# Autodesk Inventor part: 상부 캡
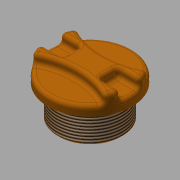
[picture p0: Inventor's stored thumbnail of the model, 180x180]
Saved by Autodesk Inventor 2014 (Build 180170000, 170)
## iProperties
Created: 2016-09
Part Number: 상부 캡
Material: PC/ABS 플라스틱
Document SubType Name: Modeling
Designer: mduedu
Density: 1.493 g/cm^3
Appearance: 주황색
Mass: 32.6937 g
Surface Area: 67.9046 cm^2
Volume: 21.898 cm^3
Author: mduedu
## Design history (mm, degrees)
sketch "스케치1"
  geometry: C1 r 22.5 at (0, 0); 1 further point
  constraints: 1 centre point, 1 coincident
  dimensions: "d0" = 45 diameter of C1
extrude "돌출1" new body sketch "스케치1" distance "d1" = 10; taper "d2" = 0 deg
sketch "스케치2" dims "d4" = 80
  geometry: C1 r 22.5 at (0, 0) reference; 3 further points
  constraints: 3 vertical alignment, 2 other
  dimensions: "d3" = 7 distance of point (0, 7) point (0, 0)
extrude "돌출2" cut sketch "스케치2" distance "d5" = 5; taper "d6" = 0 deg
sketch "스케치3"
  geometry: L1 (-22.5, 0)-(0, 0); L2 (-21.937, 5)-(-10, 5); L3 (-10, 5)-(-10, -5); L4 (-10, -5)-(-21.937, -5); A1 r 22.5 centre (0, 0) between (-19.118, 11.864) and (-19.118, -11.864) reference; A2 r 22.5 centre (0, 0) between (-21.937, 5) and (-21.937, -5); 1 further point
  constraints: 8 end point, 5 point on circle, 2 horizontal, 1 centre point, 1 coincident, 1 parallel, 1 perpendicular, 1 symmetric about line
  dimensions: "d7" = 10 distance from line of L3 point (0, 0); "d8" = 10 distance of L2.end L3.end
extrude "돌출3" cut sketch "스케치3" distance "d9" = 5; taper "d10" = 0 deg
fillet "모깎기1" dims "d11" = 2
fillet "모깎기2" dims "d12" = 2
fillet "모깎기3" dims "d13" = 2
sketch "스케치4"
  geometry: C1 r 17.5 at (0, 0); 1 further point
  constraints: 1 centre point, 1 coincident
  dimensions: "d14" = 35 diameter of C1
extrude "돌출4" join sketch "스케치4" distance "d15" = 17; taper "d16" = 0 deg
sketch "스케치5"
  geometry: C1 r 12.5 at (0, 0); 1 further point
  constraints: 1 centre point, 1 coincident
  dimensions: "d17" = 25 diameter of C1
extrude "돌출5" cut sketch "스케치5" distance "d18" = 10; taper "d19" = 0 deg
fillet "모깎기4" dims "d20" = 3
feature "스레드1" dims "d21" = 10, "d22" = 0
chamfer "모따기1" distance "d23" = 1; stored, may be unused: second distance "d24" = 2, angle "d25" = 45 deg
node "솔리드1"
mirror "대칭1"
mirror "대칭2"
node "투영된 루프1"
